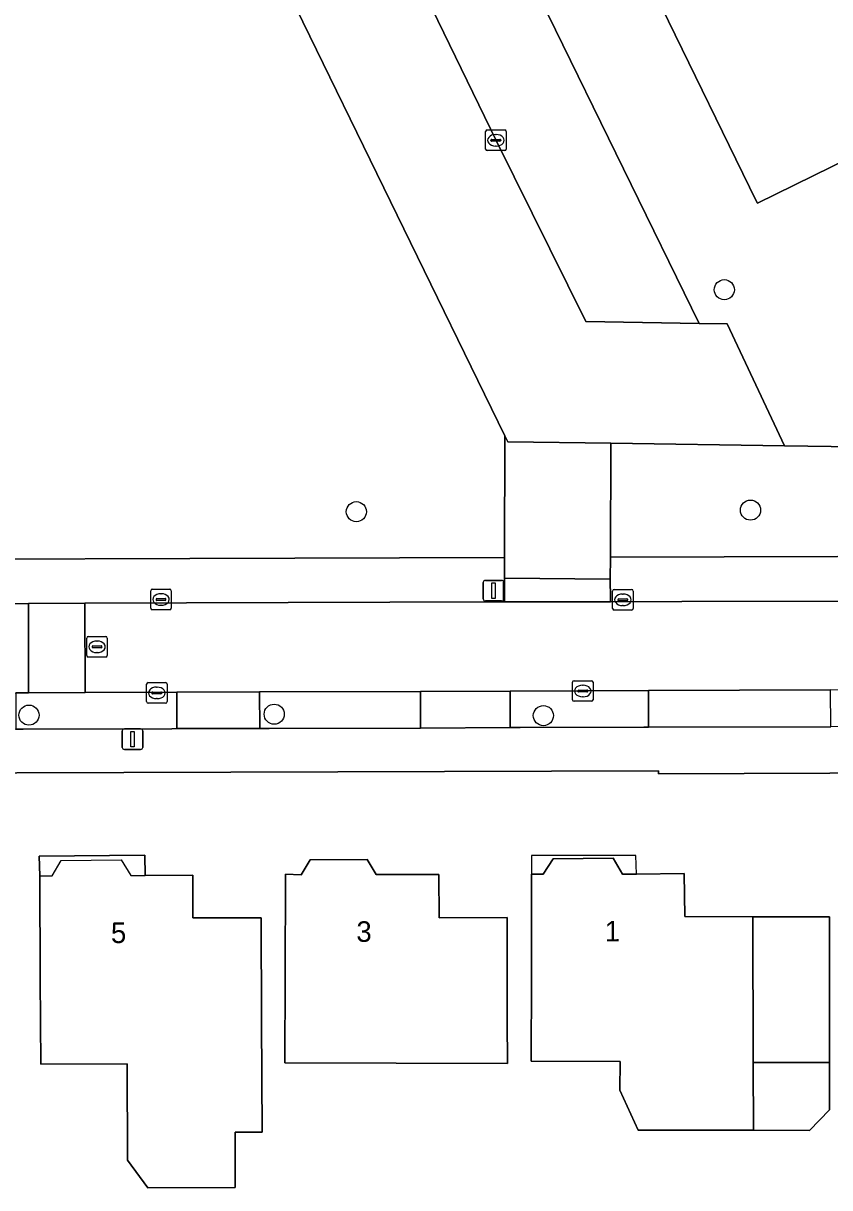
# Model space of a CAD drawing. Extents: x 160455 to 162082, y 388339 to 389736.
# Drawn here: x 160949.4 to 160988.6, y 388669.4 to 388725.9 of the extents above; entities that cross this region are included whole.
import ezdxf

# ---------------------------------------------------------------- set-up
doc = ezdxf.new("R2010")
doc.units = 0
for name, color, linetype in [('IMGEO_Boom', 7, 'Continuous'), ('IMGEO_Erf', 7, 'Continuous'), ('IMGEO_Groenvoorziening', 7, 'Continuous'), ('IMGEO_Hek', 7, 'Continuous'), ('IMGEO_Kolk', 7, 'Continuous'), ('IMGEO_Lichtmast', 7, 'Continuous'), ('IMGEO_Pand', 7, 'Continuous'), ('IMGEO_Pand_nummerreeks', 7, 'Continuous'), ('IMGEO_Pand_overbouw', 7, 'Continuous'), ('IMGEO_Parkeervlak_open', 7, 'Continuous'), ('IMGEO_Rijbaan_lokaal_open', 7, 'Continuous'), ('IMGEO_Rioolput', 7, 'Continuous'), ('IMGEO_Voetpad_open', 7, 'Continuous')]:
    doc.layers.add(name, color=color, linetype=linetype)

msp = doc.modelspace()

# ---------------------------------------------------------------- linework, layer by layer
at = {"layer": 'IMGEO_Boom'}
for centre in [(160983.456, 388713.002), (160965.574, 388702.215), (160984.729, 388702.292), (160949.664, 388692.329), (160961.584, 388692.373), (160974.663, 388692.304)]:
    msp.add_circle(centre, 0.489, dxfattribs=at)
at = {"layer": 'IMGEO_Erf'}
for points in [[(161020.621, 388731.678), (161006.266, 388761.054), (161005.821, 388761.965), (161000, 388759.109), (160981.436, 388750), (160962.382, 388740.651), (160963.059, 388739.275), (160967.518, 388741.446), (160982.232, 388711.367), (160983.598, 388711.346), (160986.381, 388705.418), (161000, 388705.227), (161020.646, 388704.937), (161020.64, 388710.846), (161020.64, 388711.063)], [(160994.446, 388721.812), (160994.186, 388722.342), (160992.005, 388721.275), (160992.265, 388720.746), (160985.061, 388717.206), (160985.007, 388717.316), (160980.412, 388726.718), (160978.766, 388730.087), (160973.602, 388740.653), (160980.818, 388744.18), (160981.077, 388743.649), (160983.269, 388744.72), (160983.009, 388745.25), (160992.728, 388750), (160999.714, 388753.414), (160999.791, 388753.452), (161000, 388753.025), (161001.478, 388750), (161004.954, 388742.889), (161006.623, 388739.473), (161011.231, 388730.046), (161000, 388724.537)], [(160959.679, 388672.057), (160959.684, 388669.372), (160955.442, 388669.364), (160954.449, 388670.709), (160954.439, 388675.376), (160950.234, 388675.367), (160950.215, 388679.517), (160950.192, 388684.516), (160950.166, 388685.48), (160955.297, 388685.519), (160955.31, 388684.538), (160957.63, 388684.55), (160957.623, 388682.48), (160960.947, 388682.476), (160960.968, 388677.477), (160960.99, 388672.06)], [(160962.104, 388675.436), (160962.119, 388679.606), (160962.136, 388684.605), (160962.886, 388684.576), (160963.328, 388685.289), (160966.102, 388685.307), (160966.533, 388684.581), (160969.585, 388684.579), (160969.603, 388682.486), (160972.904, 388682.49), (160972.91, 388677.491), (160972.913, 388675.4)], [(160979.273, 388672.162), (160978.386, 388674.105), (160978.388, 388675.504), (160974.073, 388675.51), (160974.079, 388679.598), (160974.086, 388684.597), (160974.659, 388684.606), (160975.132, 388685.342), (160978.051, 388685.374), (160978.505, 388684.6), (160979.184, 388684.606), (160981.504, 388684.625), (160981.536, 388682.536), (160984.846, 388682.532), (160988.574, 388682.527), (160988.565, 388675.448), (160988.562, 388673.146), (160987.589, 388672.15), (160984.872, 388672.154)]]:
    msp.add_lwpolyline(points, close=True, dxfattribs=at)
msp.add_lwpolyline([(161012.899, 388689.605), (161000, 388689.555), (160997.422, 388689.545), (160988.583, 388689.51), (160980.252, 388689.478), (160980.256, 388689.617), (160891.912, 388689.351)], dxfattribs=at)
at = {"layer": 'IMGEO_Groenvoorziening'}
for points in [[(160972.792, 388705.905), (160957.1, 388738.085), (160888.295, 388704.396)], [(160889.376, 388699.874), (160891.204, 388699.726), (160972.778, 388699.983), (160972.792, 388705.905)]]:
    msp.add_lwpolyline(points, dxfattribs=at)
msp.add_lwpolyline([(161020.646, 388704.937), (161000, 388705.227), (160986.381, 388705.418), (160977.941, 388705.537), (160977.918, 388699.999), (161000, 388700.069), (161012.798, 388700.109), (161020.65, 388700.126)], close=True, dxfattribs=at)
at = {"layer": 'IMGEO_Hek'}
msp.add_lwpolyline([(160983.598, 388711.346), (160986.381, 388705.418)], dxfattribs=at)
at = {"layer": 'IMGEO_Kolk'}
for p, q in [((160971.855, 388719.838), (160971.855, 388720.69)), ((160971.93, 388720.764), (160972.782, 388720.764)), ((160972.856, 388720.69), (160972.856, 388719.838)), ((160972.114, 388720.258), (160972.114, 388720.27)), ((160972.552, 388720.221), (160972.154, 388720.221)), ((160972.157, 388720.307), (160972.555, 388720.307)), ((160972.343, 388720.544), (160972.368, 388720.544)), ((160972.598, 388720.27), (160972.598, 388720.258)), ((160972.782, 388719.764), (160971.93, 388719.764)), ((160972.366, 388719.984), (160972.341, 388719.984)), ((160955.58, 388697.522), (160955.58, 388698.374)), ((160955.655, 388698.448), (160956.507, 388698.448)), ((160955.882, 388697.991), (160956.28, 388697.991)), ((160956.068, 388698.228), (160956.093, 388698.228)), ((160956.581, 388698.374), (160956.581, 388697.522)), ((160978.025, 388697.507), (160978.025, 388698.359)), ((160978.1, 388698.433), (160978.952, 388698.433)), ((160978.513, 388698.213), (160978.538, 388698.213)), ((160979.026, 388698.359), (160979.026, 388697.507)), ((160956.507, 388697.448), (160955.655, 388697.448)), ((160955.839, 388697.942), (160955.839, 388697.954)), ((160956.277, 388697.905), (160955.879, 388697.905)), ((160956.091, 388697.668), (160956.066, 388697.668)), ((160956.323, 388697.954), (160956.323, 388697.942)), ((160978.952, 388697.433), (160978.1, 388697.433)), ((160978.284, 388697.927), (160978.284, 388697.939)), ((160978.722, 388697.89), (160978.324, 388697.89)), ((160978.327, 388697.976), (160978.725, 388697.976)), ((160978.536, 388697.653), (160978.511, 388697.653)), ((160978.768, 388697.939), (160978.768, 388697.927)), ((160955.377, 388692.983), (160955.377, 388693.835)), ((160955.452, 388693.909), (160956.304, 388693.909)), ((160955.865, 388693.689), (160955.89, 388693.689)), ((160956.378, 388693.835), (160956.378, 388692.983)), ((160976.078, 388693.074), (160976.078, 388693.926)), ((160976.153, 388694), (160977.005, 388694)), ((160976.337, 388693.494), (160976.337, 388693.506)), ((160976.775, 388693.457), (160976.377, 388693.457)), ((160976.38, 388693.543), (160976.778, 388693.543)), ((160976.566, 388693.78), (160976.591, 388693.78)), ((160976.821, 388693.506), (160976.821, 388693.494)), ((160977.079, 388693.926), (160977.079, 388693.074)), ((160956.304, 388692.909), (160955.452, 388692.909)), ((160955.636, 388693.403), (160955.636, 388693.415)), ((160956.074, 388693.366), (160955.676, 388693.366)), ((160955.679, 388693.452), (160956.077, 388693.452)), ((160955.888, 388693.129), (160955.863, 388693.129)), ((160956.12, 388693.415), (160956.12, 388693.403)), ((160977.005, 388693), (160976.153, 388693)), ((160976.589, 388693.22), (160976.564, 388693.22))]:
    msp.add_line(p, q, dxfattribs=at)
for points in [[(160971.855, 388719.838), (160971.855, 388720.69)], [(160971.93, 388720.764), (160972.782, 388720.764)], [(160972.856, 388720.69), (160972.856, 388719.838)], [(160972.782, 388719.764), (160971.93, 388719.764)], [(160955.58, 388697.522), (160955.58, 388698.374)], [(160955.655, 388698.448), (160956.507, 388698.448)], [(160956.581, 388698.374), (160956.581, 388697.522)], [(160978.025, 388697.507), (160978.025, 388698.359)], [(160978.1, 388698.433), (160978.952, 388698.433)], [(160979.026, 388698.359), (160979.026, 388697.507)], [(160956.507, 388697.448), (160955.655, 388697.448)], [(160978.952, 388697.433), (160978.1, 388697.433)], [(160955.377, 388692.983), (160955.377, 388693.835)], [(160955.452, 388693.909), (160956.304, 388693.909)], [(160956.378, 388693.835), (160956.378, 388692.983)], [(160976.078, 388693.074), (160976.078, 388693.926)], [(160976.153, 388694), (160977.005, 388694)], [(160977.079, 388693.926), (160977.079, 388693.074)], [(160956.304, 388692.909), (160955.452, 388692.909)], [(160977.005, 388693), (160976.153, 388693)]]:
    msp.add_lwpolyline(points, dxfattribs=at)
for centre, radius, start, end in [((160971.932, 388720.688), 0.0765, 91.552, 178.448), ((160971.932, 388720.688), 0.0765, 91.552, 178.448), ((160972.78, 388720.688), 0.0765, 1.552, 88.448), ((160972.78, 388720.688), 0.0765, 1.552, 88.448), ((160972.154, 388720.267), 0.0403, 85.8775, 175.7526), ((160972.151, 388720.257), 0.0366, 178.938, 274.7102), ((160972.555, 388720.264), 0.043, 264.8664, 352.4533), ((160972.559, 388720.269), 0.0386, 1.7309, 96.639), ((160971.932, 388719.84), 0.0765, 181.552, 268.448), ((160971.932, 388719.84), 0.0765, 181.552, 268.448), ((160972.78, 388719.84), 0.0765, 271.552, 358.448), ((160972.78, 388719.84), 0.0765, 271.552, 358.448), ((160955.657, 388698.372), 0.0765, 91.552, 178.448), ((160955.657, 388698.372), 0.0765, 91.552, 178.448), ((160955.879, 388697.951), 0.0403, 85.8775, 175.7526), ((160956.284, 388697.953), 0.0386, 1.7309, 96.639), ((160956.505, 388698.372), 0.0765, 1.552, 88.448), ((160956.505, 388698.372), 0.0765, 1.552, 88.448), ((160978.102, 388698.357), 0.0765, 91.552, 178.448), ((160978.102, 388698.357), 0.0765, 91.552, 178.448), ((160978.95, 388698.357), 0.0765, 1.552, 88.448), ((160978.95, 388698.357), 0.0765, 1.552, 88.448), ((160955.657, 388697.524), 0.0765, 181.552, 268.448), ((160955.657, 388697.524), 0.0765, 181.552, 268.448), ((160955.876, 388697.941), 0.0366, 178.938, 274.7102), ((160956.28, 388697.948), 0.043, 264.8664, 352.4533), ((160956.505, 388697.524), 0.0765, 271.552, 358.448), ((160956.505, 388697.524), 0.0765, 271.552, 358.448), ((160978.102, 388697.509), 0.0765, 181.552, 268.448), ((160978.102, 388697.509), 0.0765, 181.552, 268.448), ((160978.324, 388697.936), 0.0403, 85.8775, 175.7526), ((160978.321, 388697.926), 0.0366, 178.938, 274.7102), ((160978.725, 388697.933), 0.043, 264.8664, 352.4533), ((160978.729, 388697.938), 0.0386, 1.7309, 96.639), ((160978.95, 388697.509), 0.0765, 271.552, 358.448), ((160978.95, 388697.509), 0.0765, 271.552, 358.448), ((160955.454, 388693.833), 0.0765, 91.552, 178.448), ((160955.454, 388693.833), 0.0765, 91.552, 178.448), ((160956.302, 388693.833), 0.0765, 1.552, 88.448), ((160956.302, 388693.833), 0.0765, 1.552, 88.448), ((160976.155, 388693.924), 0.0765, 91.552, 178.448), ((160976.155, 388693.924), 0.0765, 91.552, 178.448), ((160976.377, 388693.503), 0.0403, 85.8775, 175.7526), ((160976.374, 388693.493), 0.0366, 178.938, 274.7102), ((160976.778, 388693.5), 0.043, 264.8664, 352.4533), ((160976.782, 388693.505), 0.0386, 1.7309, 96.639), ((160977.003, 388693.924), 0.0765, 1.552, 88.448), ((160977.003, 388693.924), 0.0765, 1.552, 88.448), ((160955.454, 388692.985), 0.0765, 181.552, 268.448), ((160955.454, 388692.985), 0.0765, 181.552, 268.448), ((160955.676, 388693.412), 0.0403, 85.8775, 175.7526), ((160955.673, 388693.402), 0.0366, 178.938, 274.7102), ((160956.077, 388693.409), 0.043, 264.8664, 352.4533), ((160956.081, 388693.414), 0.0386, 1.7309, 96.639), ((160956.302, 388692.985), 0.0765, 271.552, 358.448), ((160956.302, 388692.985), 0.0765, 271.552, 358.448), ((160976.155, 388693.076), 0.0765, 181.552, 268.448), ((160976.155, 388693.076), 0.0765, 181.552, 268.448), ((160977.003, 388693.076), 0.0765, 271.552, 358.448), ((160977.003, 388693.076), 0.0765, 271.552, 358.448)]:
    msp.add_arc(centre, radius, start, end, dxfattribs=at)
for centre, major_axis, ratio, start_param, end_param in [((160972.342, 388720.264), (-0.387, 0.002), 0.722429, 4.712389, 7.853982), ((160972.367, 388720.264), (-0.39, 0.002), 0.717154, 1.570796, 4.712389), ((160956.067, 388697.948), (-0.387, 0.002), 0.722429, 4.712389, 7.853982), ((160956.092, 388697.948), (-0.39, 0.002), 0.717154, 1.570796, 4.712389), ((160978.512, 388697.933), (-0.387, 0.002), 0.722429, 4.712389, 7.853982), ((160978.537, 388697.933), (-0.39, 0.002), 0.717154, 1.570796, 4.712389), ((160955.864, 388693.409), (-0.387, 0.002), 0.722429, 4.712389, 7.853982), ((160955.889, 388693.409), (-0.39, 0.002), 0.717154, 1.570796, 4.712389), ((160976.565, 388693.5), (-0.387, 0.002), 0.722429, 4.712389, 7.853982), ((160976.59, 388693.5), (-0.39, 0.002), 0.717154, 1.570796, 4.712389)]:
    msp.add_ellipse(centre, major_axis=major_axis, ratio=ratio, start_param=start_param, end_param=end_param, dxfattribs=at)
at = {"layer": 'IMGEO_Lichtmast'}
for p, q in [((160971.743, 388697.976), (160971.743, 388698.776)), ((160971.743, 388698.776), (160971.743, 388697.976)), ((160971.843, 388698.876), (160972.633, 388698.876)), ((160972.633, 388698.876), (160971.843, 388698.876)), ((160972.733, 388698.776), (160972.733, 388697.976)), ((160972.733, 388697.976), (160972.733, 388698.776)), ((160972.633, 388697.876), (160971.843, 388697.876)), ((160971.843, 388697.876), (160972.633, 388697.876)), ((160954.2, 388690.761), (160954.2, 388691.561)), ((160954.2, 388691.561), (160954.2, 388690.761)), ((160954.3, 388691.661), (160955.09, 388691.661)), ((160955.09, 388691.661), (160954.3, 388691.661)), ((160955.19, 388691.561), (160955.19, 388690.761)), ((160955.19, 388690.761), (160955.19, 388691.561)), ((160955.09, 388690.661), (160954.3, 388690.661)), ((160954.3, 388690.661), (160955.09, 388690.661))]:
    msp.add_line(p, q, dxfattribs=at)
for points in [[(160972.163, 388698.751), (160972.313, 388698.751), (160972.313, 388698.001), (160972.163, 388698.001), (160972.163, 388698.751)], [(160954.62, 388691.536), (160954.77, 388691.536), (160954.77, 388690.786), (160954.62, 388690.786), (160954.62, 388691.536)]]:
    msp.add_lwpolyline(points, dxfattribs=at)
for centre, start, end in [((160971.843, 388698.776), 90, 180), ((160971.843, 388698.776), 90, 180), ((160972.633, 388698.776), 0, 90), ((160972.633, 388698.776), 360, 90), ((160971.843, 388697.976), 180, 270), ((160971.843, 388697.976), 180, 270), ((160972.633, 388697.976), 270, 0), ((160972.633, 388697.976), 270, 0), ((160954.3, 388691.561), 90, 180), ((160954.3, 388691.561), 90, 180), ((160955.09, 388691.561), 0, 90), ((160955.09, 388691.561), 360, 90), ((160954.3, 388690.761), 180, 270), ((160954.3, 388690.761), 180, 270), ((160955.09, 388690.761), 270, 0), ((160955.09, 388690.761), 270, 0)]:
    msp.add_arc(centre, 0.1, start, end, dxfattribs=at)
at = {"layer": 'IMGEO_Pand'}
for points in [[(160983.009, 388745.25), (160983.269, 388744.72), (160981.077, 388743.649), (160980.818, 388744.18), (160973.602, 388740.653), (160978.766, 388730.087), (160980.412, 388726.718), (160985.007, 388717.316), (160985.061, 388717.206), (160992.265, 388720.746), (160992.005, 388721.275), (160994.186, 388722.342), (160994.446, 388721.812), (161000, 388724.537), (161011.231, 388730.046), (161006.623, 388739.473), (161004.954, 388742.889), (161001.478, 388750), (161000, 388753.025), (160999.791, 388753.452), (160999.714, 388753.414), (160992.728, 388750)], [(160954.439, 388675.376), (160954.449, 388670.709), (160955.442, 388669.364), (160959.684, 388669.372), (160959.679, 388672.057), (160960.99, 388672.06), (160960.968, 388677.477), (160960.947, 388682.476), (160957.623, 388682.48), (160957.63, 388684.55), (160955.31, 388684.538), (160955.297, 388685.519), (160950.166, 388685.48), (160950.192, 388684.516), (160950.215, 388679.517), (160950.234, 388675.367)], [(160962.119, 388679.606), (160962.104, 388675.436), (160972.913, 388675.4), (160972.91, 388677.491), (160972.904, 388682.49), (160969.603, 388682.486), (160969.585, 388684.579), (160966.533, 388684.581), (160966.102, 388685.307), (160963.328, 388685.289), (160962.886, 388684.576), (160962.136, 388684.605)], [(160984.864, 388675.453), (160984.846, 388682.532), (160981.536, 388682.536), (160981.504, 388684.625), (160979.184, 388684.606), (160978.505, 388684.6), (160978.051, 388685.374), (160975.132, 388685.342), (160974.659, 388684.606), (160974.086, 388684.597), (160974.079, 388679.598), (160974.073, 388675.51), (160978.388, 388675.504), (160978.386, 388674.105), (160979.273, 388672.162), (160984.872, 388672.154)], [(160984.864, 388675.453), (160988.565, 388675.448), (160988.574, 388682.527), (160984.846, 388682.532)], [(160984.864, 388675.453), (160984.872, 388672.154), (160987.589, 388672.15), (160988.562, 388673.146), (160988.565, 388675.448)]]:
    msp.add_lwpolyline(points, close=True, dxfattribs=at)
at = {"layer": 'IMGEO_Pand_overbouw'}
for points in [[(160950.192, 388684.516), (160950.786, 388684.525), (160951.23, 388685.272), (160954.144, 388685.289), (160954.611, 388684.534), (160955.31, 388684.538), (160955.297, 388685.519), (160950.166, 388685.48)], [(160974.086, 388684.597), (160974.659, 388684.606), (160975.132, 388685.342), (160978.051, 388685.374), (160978.505, 388684.6), (160979.184, 388684.606), (160979.164, 388685.511), (160974.08, 388685.501)]]:
    msp.add_lwpolyline(points, close=True, dxfattribs=at)
at = {"layer": 'IMGEO_Parkeervlak_open'}
for points in [[(160982.232, 388711.367), (160967.518, 388741.446), (160963.059, 388739.275), (160968.684, 388727.84), (160972.373, 388720.249), (160976.723, 388711.453)], [(160968.686, 388693.483), (160960.871, 388693.455), (160960.877, 388691.679), (160961.34, 388691.68), (160968.692, 388691.702)], [(160979.77, 388693.523), (160973.041, 388693.499), (160973.048, 388691.732), (160973.529, 388691.735), (160979.549, 388691.741), (160979.777, 388691.741)], [(160956.849, 388693.44), (160952.397, 388693.424), (160949.647, 388693.414), (160949.022, 388693.412), (160949.028, 388691.651), (160949.377, 388691.654), (160956.599, 388691.67), (160956.855, 388691.671)]]:
    msp.add_lwpolyline(points, close=True, dxfattribs=at)
at = {"layer": 'IMGEO_Rijbaan_lokaal_open'}
for points in [[(160963.059, 388739.275), (160962.382, 388740.651), (160957.1, 388738.085), (160972.792, 388705.905), (160972.937, 388705.607), (160977.941, 388705.537), (160986.381, 388705.418), (160983.598, 388711.346), (160982.232, 388711.367), (160976.723, 388711.453), (160972.373, 388720.249), (160968.684, 388727.84)], [(161009.246, 388697.99), (161004.354, 388697.923), (160991.997, 388697.868), (160981.384, 388697.846), (160977.921, 388697.839), (160972.781, 388697.828), (160972.148, 388697.827), (160952.384, 388697.763), (160952.397, 388693.424), (160956.849, 388693.44), (160960.871, 388693.455), (160968.686, 388693.483), (160973.041, 388693.499), (160979.77, 388693.523), (160988.624, 388693.555), (161000, 388693.596), (161009.273, 388693.63)], [(160949.634, 388697.755), (160894.543, 388697.579), (160894.516, 388693.27), (160894.619, 388693.27), (160908.612, 388693.306), (160914.036, 388693.32), (160920.551, 388693.336), (160925.216, 388693.348), (160932.462, 388693.366), (160936.749, 388693.377), (160945.454, 388693.399), (160945.708, 388693.4), (160949.022, 388693.412), (160949.647, 388693.414)], [(160952.384, 388697.763), (160949.634, 388697.755), (160949.647, 388693.414), (160952.397, 388693.424)]]:
    msp.add_lwpolyline(points, close=True, dxfattribs=at)
at = {"layer": 'IMGEO_Rioolput'}
for p, q in [((160952.47, 388695.223), (160952.47, 388696.075)), ((160952.545, 388696.149), (160953.397, 388696.149)), ((160952.958, 388695.929), (160952.983, 388695.929)), ((160953.471, 388696.075), (160953.471, 388695.223)), ((160952.729, 388695.643), (160952.729, 388695.655)), ((160953.167, 388695.606), (160952.769, 388695.606)), ((160952.772, 388695.692), (160953.17, 388695.692)), ((160952.981, 388695.369), (160952.956, 388695.369)), ((160953.213, 388695.655), (160953.213, 388695.643)), ((160953.397, 388695.149), (160952.545, 388695.149))]:
    msp.add_line(p, q, dxfattribs=at)
for points in [[(160952.47, 388695.223), (160952.47, 388696.075)], [(160952.545, 388696.149), (160953.397, 388696.149)], [(160953.471, 388696.075), (160953.471, 388695.223)], [(160953.397, 388695.149), (160952.545, 388695.149)]]:
    msp.add_lwpolyline(points, dxfattribs=at)
for centre, radius, start, end in [((160952.547, 388696.073), 0.0765, 91.552, 178.448), ((160952.547, 388696.073), 0.0765, 91.552, 178.448), ((160953.395, 388696.073), 0.0765, 1.552, 88.448), ((160953.395, 388696.073), 0.0765, 1.552, 88.448), ((160952.547, 388695.225), 0.0765, 181.552, 268.448), ((160952.547, 388695.225), 0.0765, 181.552, 268.448), ((160952.769, 388695.652), 0.0403, 85.8775, 175.7526), ((160952.766, 388695.642), 0.0366, 178.938, 274.7102), ((160953.17, 388695.649), 0.043, 264.8664, 352.4533), ((160953.174, 388695.654), 0.0386, 1.7309, 96.639), ((160953.395, 388695.225), 0.0765, 271.552, 358.448), ((160953.395, 388695.225), 0.0765, 271.552, 358.448)]:
    msp.add_arc(centre, radius, start, end, dxfattribs=at)
for centre, major_axis, ratio, start_param, end_param in [((160952.957, 388695.649), (-0.387, 0.002), 0.722429, 4.712389, 7.853982), ((160952.982, 388695.649), (-0.39, 0.002), 0.717154, 1.570796, 4.712389)]:
    msp.add_ellipse(centre, major_axis=major_axis, ratio=ratio, start_param=start_param, end_param=end_param, dxfattribs=at)
at = {"layer": 'IMGEO_Voetpad_open'}
for points in [[(160977.941, 388705.537), (160972.937, 388705.607), (160972.792, 388705.905), (160972.778, 388699.983), (160972.776, 388698.985), (160977.914, 388698.938), (160977.918, 388699.999)], [(160972.778, 388699.983), (160891.204, 388699.726), (160889.376, 388699.874), (160888.722, 388697.56), (160894.543, 388697.579), (160949.634, 388697.755), (160952.384, 388697.763), (160972.148, 388697.827), (160972.781, 388697.828), (160972.781, 388698.001), (160972.776, 388698.985)], [(160977.914, 388698.938), (160972.776, 388698.985), (160972.781, 388698.001), (160972.781, 388697.828), (160977.921, 388697.839), (160977.921, 388698.02)], [(160973.041, 388693.499), (160968.686, 388693.483), (160968.692, 388691.702), (160973.048, 388691.732)], [(160988.624, 388693.555), (160979.77, 388693.523), (160979.777, 388691.741), (160988.63, 388691.757)], [(160960.871, 388693.455), (160956.849, 388693.44), (160956.855, 388691.671), (160960.877, 388691.679)]]:
    msp.add_lwpolyline(points, close=True, dxfattribs=at)
for points in [[(161024.549, 388700.134), (161020.65, 388700.126), (161012.798, 388700.109), (161000, 388700.069), (160977.918, 388699.999), (160977.914, 388698.938), (160977.921, 388698.02), (160977.921, 388697.839), (160981.384, 388697.846), (160991.997, 388697.868), (161004.354, 388697.923), (161009.246, 388697.99), (161012.631, 388698.036), (161015.214, 388698.16)], [(161006.155, 388691.825), (161000, 388691.801), (160988.63, 388691.757), (160979.777, 388691.741), (160979.549, 388691.741), (160973.529, 388691.735)], [(160889.873, 388691.456), (160891.912, 388689.351), (160980.256, 388689.617), (160980.252, 388689.478), (160988.583, 388689.51), (160997.422, 388689.545), (161000, 388689.555), (161012.899, 388689.605)], [(160973.529, 388691.735), (160973.048, 388691.732), (160968.692, 388691.702), (160961.34, 388691.68), (160960.877, 388691.679), (160956.855, 388691.671), (160956.599, 388691.67), (160949.377, 388691.654), (160949.028, 388691.651), (160945.715, 388691.626), (160945.469, 388691.624), (160937.292, 388691.588), (160936.754, 388691.588), (160932.467, 388691.591), (160925.221, 388691.559), (160920.556, 388691.539), (160920.383, 388691.538), (160914.041, 388691.53), (160908.617, 388691.513), (160908.287, 388691.512), (160897.679, 388691.489)]]:
    msp.add_lwpolyline(points, dxfattribs=at)

# ---------------------------------------------------------------- texts
at = {"layer": 'IMGEO_Pand_nummerreeks'}
for s, rotation, p in [('5', 0.2636, (160953.651, 388681.251)), ('3', 359.8, (160965.574, 388681.313)), ('1', 0.2163, (160977.647, 388681.331))]:
    msp.add_text(s, height=1, rotation=rotation, dxfattribs=at).set_placement(p)

doc.saveas('drawing.dxf')
